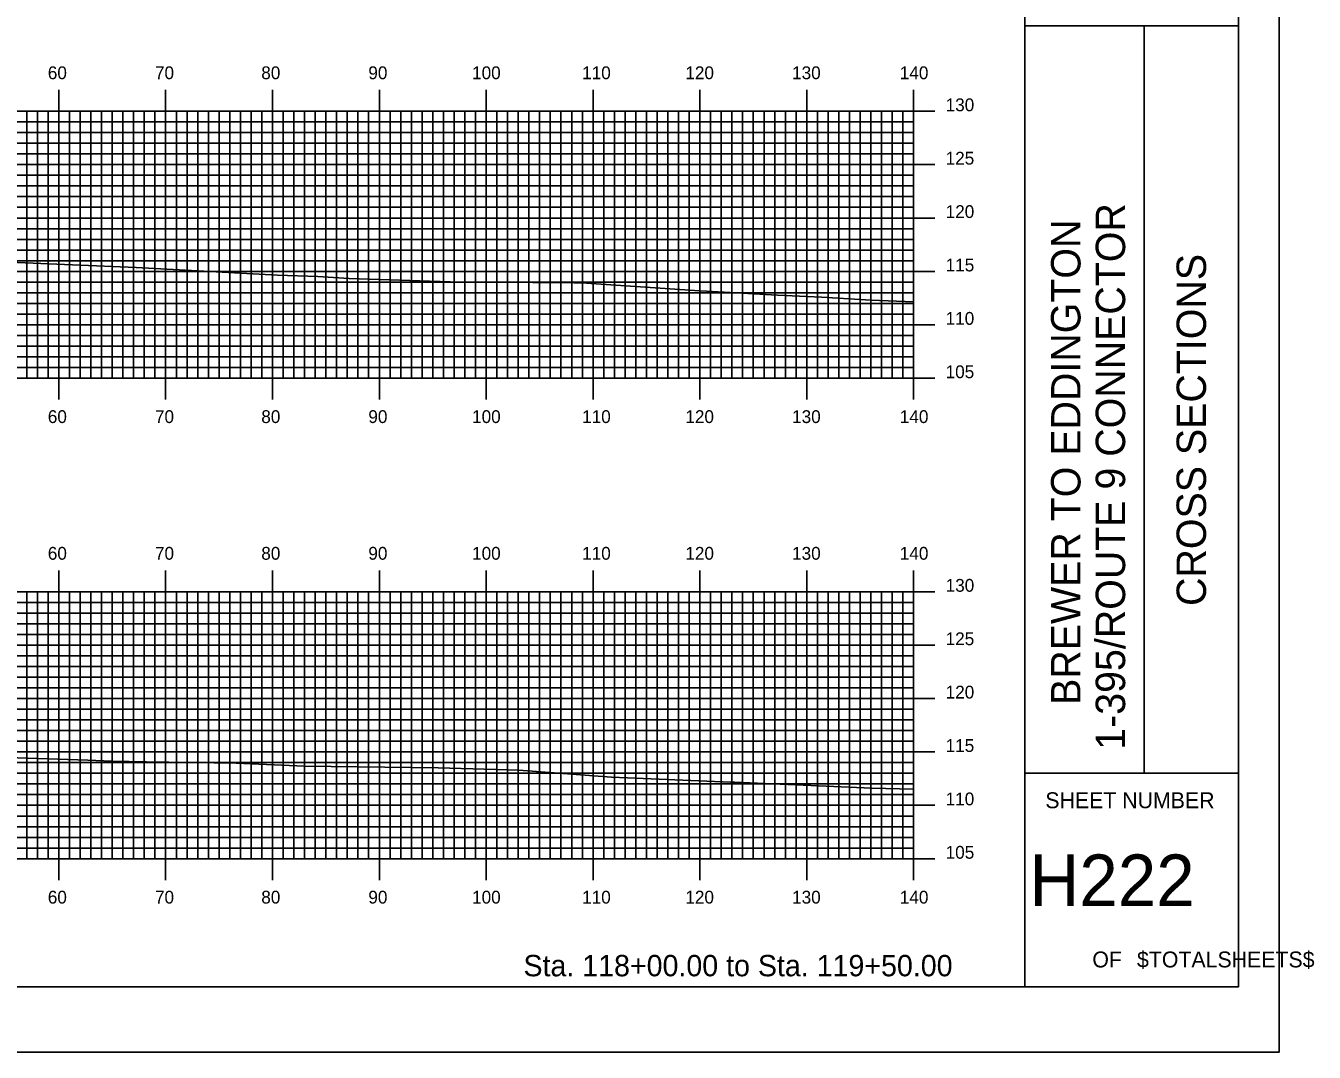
# Model space of a CAD drawing. Extents: x 1771629 to 1771972, y 442591 to 442811.
# Drawn here: x 1771851.5 to 1771972.1, y 442590.5 to 442686.7 of the extents above; entities that cross this region are included whole.
import ezdxf

# ---------------------------------------------------------------- set-up
doc = ezdxf.new("R2010")
doc.units = 0
for name, color, linetype in [('BORDER', 7, 'Continuous'), ('H_V ANNOTATION', 7, 'Continuous'), ('MAJOR', 7, 'Continuous'), ('MINOR', 7, 'Continuous'), ('PLOT BOUNDARY', 7, 'Continuous'), ('S_Roadway_Centerline', 7, 'Continuous')]:
    doc.layers.add(name, color=color, linetype=linetype)

msp = doc.modelspace()

# ---------------------------------------------------------------- linework, layer by layer
at = {"layer": 'BORDER'}
for p, q in [((1771944.98, 442596.67), (1771944.98, 442806.67)), ((1771944.98, 442686.67), (1771964.98, 442686.67)), ((1771956.16, 442616.67), (1771956.16, 442686.67)), ((1771944.98, 442616.67), (1771964.98, 442616.67))]:
    msp.add_line(p, q, dxfattribs=at)
msp.add_lwpolyline([(1771644.98, 442596.67), (1771964.98, 442596.67), (1771964.98, 442806.67), (1771644.98, 442806.67)], close=True, dxfattribs=at)
at = {"layer": 'MAJOR'}
for p, q in [((1771854.58, 442680.67), (1771854.58, 442678.67)), ((1771864.58, 442680.67), (1771864.58, 442678.67)), ((1771874.58, 442680.67), (1771874.58, 442678.67)), ((1771884.58, 442680.67), (1771884.58, 442678.67)), ((1771894.58, 442680.67), (1771894.58, 442678.67)), ((1771904.58, 442680.67), (1771904.58, 442678.67)), ((1771914.58, 442680.67), (1771914.58, 442678.67)), ((1771924.58, 442680.67), (1771924.58, 442678.67)), ((1771934.58, 442680.67), (1771934.58, 442678.67)), ((1771654.58, 442678.67), (1771934.58, 442678.67)), ((1771654.58, 442678.67), (1771934.58, 442678.67)), ((1771854.58, 442653.67), (1771854.58, 442678.67)), ((1771864.58, 442653.67), (1771864.58, 442678.67)), ((1771874.58, 442653.67), (1771874.58, 442678.67)), ((1771884.58, 442653.67), (1771884.58, 442678.67)), ((1771894.58, 442653.67), (1771894.58, 442678.67)), ((1771904.58, 442653.67), (1771904.58, 442678.67)), ((1771914.58, 442653.67), (1771914.58, 442678.67)), ((1771924.58, 442653.67), (1771924.58, 442678.67)), ((1771936.58, 442678.67), (1771932.58, 442678.67)), ((1771934.58, 442653.67), (1771934.58, 442678.67)), ((1771934.58, 442653.67), (1771934.58, 442678.67)), ((1771654.58, 442673.67), (1771934.58, 442673.67)), ((1771936.58, 442673.67), (1771932.58, 442673.67)), ((1771654.58, 442668.67), (1771934.58, 442668.67)), ((1771936.58, 442668.67), (1771932.58, 442668.67)), ((1771654.58, 442663.67), (1771934.58, 442663.67)), ((1771936.58, 442663.67), (1771932.58, 442663.67)), ((1771654.58, 442658.67), (1771934.58, 442658.67)), ((1771936.58, 442658.67), (1771932.58, 442658.67)), ((1771654.58, 442653.67), (1771934.58, 442653.67)), ((1771654.58, 442653.67), (1771934.58, 442653.67)), ((1771854.58, 442651.66), (1771854.58, 442653.67)), ((1771864.58, 442651.66), (1771864.58, 442653.67)), ((1771874.58, 442651.66), (1771874.58, 442653.67)), ((1771884.58, 442651.66), (1771884.58, 442653.67)), ((1771894.58, 442651.66), (1771894.58, 442653.67)), ((1771904.58, 442651.66), (1771904.58, 442653.67)), ((1771914.58, 442651.66), (1771914.58, 442653.67)), ((1771924.58, 442651.66), (1771924.58, 442653.67)), ((1771936.58, 442653.67), (1771932.58, 442653.67)), ((1771934.58, 442651.66), (1771934.58, 442653.67)), ((1771854.58, 442635.67), (1771854.58, 442633.67)), ((1771864.58, 442635.67), (1771864.58, 442633.67)), ((1771874.58, 442635.67), (1771874.58, 442633.67)), ((1771884.58, 442635.67), (1771884.58, 442633.67)), ((1771894.58, 442635.67), (1771894.58, 442633.67)), ((1771904.58, 442635.67), (1771904.58, 442633.67)), ((1771914.58, 442635.67), (1771914.58, 442633.67)), ((1771924.58, 442635.67), (1771924.58, 442633.67)), ((1771934.58, 442635.67), (1771934.58, 442633.67)), ((1771654.58, 442633.67), (1771934.58, 442633.67)), ((1771654.58, 442633.67), (1771934.58, 442633.67)), ((1771854.58, 442608.67), (1771854.58, 442633.67)), ((1771864.58, 442608.67), (1771864.58, 442633.67)), ((1771874.58, 442608.67), (1771874.58, 442633.67)), ((1771884.58, 442608.67), (1771884.58, 442633.67)), ((1771894.58, 442608.67), (1771894.58, 442633.67)), ((1771904.58, 442608.67), (1771904.58, 442633.67)), ((1771914.58, 442608.67), (1771914.58, 442633.67)), ((1771924.58, 442608.67), (1771924.58, 442633.67)), ((1771936.58, 442633.67), (1771932.58, 442633.67)), ((1771934.58, 442608.67), (1771934.58, 442633.67)), ((1771934.58, 442608.67), (1771934.58, 442633.67)), ((1771654.58, 442628.67), (1771934.58, 442628.67)), ((1771936.58, 442628.67), (1771932.58, 442628.67)), ((1771654.58, 442623.67), (1771934.58, 442623.67)), ((1771936.58, 442623.67), (1771932.58, 442623.67)), ((1771654.58, 442618.67), (1771934.58, 442618.67)), ((1771936.58, 442618.67), (1771932.58, 442618.67)), ((1771654.58, 442613.67), (1771934.58, 442613.67)), ((1771936.58, 442613.67), (1771932.58, 442613.67)), ((1771654.58, 442608.67), (1771934.58, 442608.67)), ((1771654.58, 442608.67), (1771934.58, 442608.67)), ((1771854.58, 442606.66), (1771854.58, 442608.67)), ((1771864.58, 442606.66), (1771864.58, 442608.67)), ((1771874.58, 442606.66), (1771874.58, 442608.67)), ((1771884.58, 442606.66), (1771884.58, 442608.67)), ((1771894.58, 442606.66), (1771894.58, 442608.67)), ((1771904.58, 442606.66), (1771904.58, 442608.67)), ((1771914.58, 442606.66), (1771914.58, 442608.67)), ((1771924.58, 442606.66), (1771924.58, 442608.67)), ((1771936.58, 442608.67), (1771932.58, 442608.67)), ((1771934.58, 442606.66), (1771934.58, 442608.67))]:
    msp.add_line(p, q, dxfattribs=at)
at = {"layer": 'MINOR'}
for p, q in [((1771851.58, 442653.67), (1771851.58, 442678.67)), ((1771852.58, 442653.67), (1771852.58, 442678.67)), ((1771853.58, 442653.67), (1771853.58, 442678.67)), ((1771855.58, 442653.67), (1771855.58, 442678.67)), ((1771856.58, 442653.67), (1771856.58, 442678.67)), ((1771857.58, 442653.67), (1771857.58, 442678.67)), ((1771858.58, 442653.67), (1771858.58, 442678.67)), ((1771859.58, 442653.67), (1771859.58, 442678.67)), ((1771860.58, 442653.67), (1771860.58, 442678.67)), ((1771861.58, 442653.67), (1771861.58, 442678.67)), ((1771862.58, 442653.67), (1771862.58, 442678.67)), ((1771863.58, 442653.67), (1771863.58, 442678.67)), ((1771865.58, 442653.67), (1771865.58, 442678.67)), ((1771866.58, 442653.67), (1771866.58, 442678.67)), ((1771867.58, 442653.67), (1771867.58, 442678.67)), ((1771868.58, 442653.67), (1771868.58, 442678.67)), ((1771869.58, 442653.67), (1771869.58, 442678.67)), ((1771870.58, 442653.67), (1771870.58, 442678.67)), ((1771871.58, 442653.67), (1771871.58, 442678.67)), ((1771872.58, 442653.67), (1771872.58, 442678.67)), ((1771873.58, 442653.67), (1771873.58, 442678.67)), ((1771875.58, 442653.67), (1771875.58, 442678.67)), ((1771876.58, 442653.67), (1771876.58, 442678.67)), ((1771877.58, 442653.67), (1771877.58, 442678.67)), ((1771878.58, 442653.67), (1771878.58, 442678.67)), ((1771879.58, 442653.67), (1771879.58, 442678.67)), ((1771880.58, 442653.67), (1771880.58, 442678.67)), ((1771881.58, 442653.67), (1771881.58, 442678.67)), ((1771882.58, 442653.67), (1771882.58, 442678.67)), ((1771883.58, 442653.67), (1771883.58, 442678.67)), ((1771885.58, 442653.67), (1771885.58, 442678.67)), ((1771886.58, 442653.67), (1771886.58, 442678.67)), ((1771887.58, 442653.67), (1771887.58, 442678.67)), ((1771888.58, 442653.67), (1771888.58, 442678.67)), ((1771889.58, 442653.67), (1771889.58, 442678.67)), ((1771890.58, 442653.67), (1771890.58, 442678.67)), ((1771891.58, 442653.67), (1771891.58, 442678.67)), ((1771892.58, 442653.67), (1771892.58, 442678.67)), ((1771893.58, 442653.67), (1771893.58, 442678.67)), ((1771895.58, 442653.67), (1771895.58, 442678.67)), ((1771896.58, 442653.67), (1771896.58, 442678.67)), ((1771897.58, 442653.67), (1771897.58, 442678.67)), ((1771898.58, 442653.67), (1771898.58, 442678.67)), ((1771899.58, 442653.67), (1771899.58, 442678.67)), ((1771900.58, 442653.67), (1771900.58, 442678.67)), ((1771901.58, 442653.67), (1771901.58, 442678.67)), ((1771902.58, 442653.67), (1771902.58, 442678.67)), ((1771903.58, 442653.67), (1771903.58, 442678.67)), ((1771905.58, 442653.67), (1771905.58, 442678.67)), ((1771906.58, 442653.67), (1771906.58, 442678.67)), ((1771907.58, 442653.67), (1771907.58, 442678.67)), ((1771908.58, 442653.67), (1771908.58, 442678.67)), ((1771909.58, 442653.67), (1771909.58, 442678.67)), ((1771910.58, 442653.67), (1771910.58, 442678.67)), ((1771911.58, 442653.67), (1771911.58, 442678.67)), ((1771912.58, 442653.67), (1771912.58, 442678.67)), ((1771913.58, 442653.67), (1771913.58, 442678.67)), ((1771915.58, 442653.67), (1771915.58, 442678.67)), ((1771916.58, 442653.67), (1771916.58, 442678.67)), ((1771917.58, 442653.67), (1771917.58, 442678.67)), ((1771918.58, 442653.67), (1771918.58, 442678.67)), ((1771919.58, 442653.67), (1771919.58, 442678.67)), ((1771920.58, 442653.67), (1771920.58, 442678.67)), ((1771921.58, 442653.67), (1771921.58, 442678.67)), ((1771922.58, 442653.67), (1771922.58, 442678.67)), ((1771923.58, 442653.67), (1771923.58, 442678.67)), ((1771925.58, 442653.67), (1771925.58, 442678.67)), ((1771926.58, 442653.67), (1771926.58, 442678.67)), ((1771927.58, 442653.67), (1771927.58, 442678.67)), ((1771928.58, 442653.67), (1771928.58, 442678.67)), ((1771929.58, 442653.67), (1771929.58, 442678.67)), ((1771930.58, 442653.67), (1771930.58, 442678.67)), ((1771931.58, 442653.67), (1771931.58, 442678.67)), ((1771932.58, 442653.67), (1771932.58, 442678.67)), ((1771933.58, 442653.67), (1771933.58, 442678.67)), ((1771654.58, 442677.67), (1771934.58, 442677.67)), ((1771934.58, 442677.67), (1771932.58, 442677.67)), ((1771654.58, 442676.67), (1771934.58, 442676.67)), ((1771654.58, 442675.67), (1771934.58, 442675.67)), ((1771934.58, 442676.67), (1771932.58, 442676.67)), ((1771934.58, 442675.67), (1771932.58, 442675.67)), ((1771654.58, 442674.67), (1771934.58, 442674.67)), ((1771934.58, 442674.67), (1771932.58, 442674.67)), ((1771654.58, 442672.67), (1771934.58, 442672.67)), ((1771934.58, 442672.67), (1771932.58, 442672.67)), ((1771654.58, 442671.67), (1771934.58, 442671.67)), ((1771934.58, 442671.67), (1771932.58, 442671.67)), ((1771654.58, 442670.67), (1771934.58, 442670.67)), ((1771654.58, 442669.67), (1771934.58, 442669.67)), ((1771934.58, 442670.67), (1771932.58, 442670.67)), ((1771934.58, 442669.67), (1771932.58, 442669.67)), ((1771654.58, 442667.67), (1771934.58, 442667.67)), ((1771934.58, 442667.67), (1771932.58, 442667.67)), ((1771654.58, 442666.67), (1771934.58, 442666.67)), ((1771934.58, 442666.67), (1771932.58, 442666.67)), ((1771654.58, 442665.67), (1771934.58, 442665.67)), ((1771934.58, 442665.67), (1771932.58, 442665.67)), ((1771654.58, 442664.67), (1771934.58, 442664.67)), ((1771934.58, 442664.67), (1771932.58, 442664.67)), ((1771654.58, 442662.67), (1771934.58, 442662.67)), ((1771934.58, 442662.67), (1771932.58, 442662.67)), ((1771654.58, 442661.67), (1771934.58, 442661.67)), ((1771934.58, 442661.67), (1771932.58, 442661.67)), ((1771654.58, 442660.67), (1771934.58, 442660.67)), ((1771934.58, 442660.67), (1771932.58, 442660.67)), ((1771654.58, 442659.67), (1771934.58, 442659.67)), ((1771934.58, 442659.67), (1771932.58, 442659.67)), ((1771654.58, 442657.67), (1771934.58, 442657.67)), ((1771934.58, 442657.67), (1771932.58, 442657.67)), ((1771654.58, 442656.67), (1771934.58, 442656.67)), ((1771934.58, 442656.67), (1771932.58, 442656.67)), ((1771654.58, 442655.67), (1771934.58, 442655.67)), ((1771934.58, 442655.67), (1771932.58, 442655.67)), ((1771654.58, 442654.67), (1771934.58, 442654.67)), ((1771934.58, 442654.67), (1771932.58, 442654.67)), ((1771851.58, 442608.67), (1771851.58, 442633.67)), ((1771852.58, 442608.67), (1771852.58, 442633.67)), ((1771853.58, 442608.67), (1771853.58, 442633.67)), ((1771855.58, 442608.67), (1771855.58, 442633.67)), ((1771856.58, 442608.67), (1771856.58, 442633.67)), ((1771857.58, 442608.67), (1771857.58, 442633.67)), ((1771858.58, 442608.67), (1771858.58, 442633.67)), ((1771859.58, 442608.67), (1771859.58, 442633.67)), ((1771860.58, 442608.67), (1771860.58, 442633.67)), ((1771861.58, 442608.67), (1771861.58, 442633.67)), ((1771862.58, 442608.67), (1771862.58, 442633.67)), ((1771863.58, 442608.67), (1771863.58, 442633.67)), ((1771865.58, 442608.67), (1771865.58, 442633.67)), ((1771866.58, 442608.67), (1771866.58, 442633.67)), ((1771867.58, 442608.67), (1771867.58, 442633.67)), ((1771868.58, 442608.67), (1771868.58, 442633.67)), ((1771869.58, 442608.67), (1771869.58, 442633.67)), ((1771870.58, 442608.67), (1771870.58, 442633.67)), ((1771871.58, 442608.67), (1771871.58, 442633.67)), ((1771872.58, 442608.67), (1771872.58, 442633.67)), ((1771873.58, 442608.67), (1771873.58, 442633.67)), ((1771875.58, 442608.67), (1771875.58, 442633.67)), ((1771876.58, 442608.67), (1771876.58, 442633.67)), ((1771877.58, 442608.67), (1771877.58, 442633.67)), ((1771878.58, 442608.67), (1771878.58, 442633.67)), ((1771879.58, 442608.67), (1771879.58, 442633.67)), ((1771880.58, 442608.67), (1771880.58, 442633.67)), ((1771881.58, 442608.67), (1771881.58, 442633.67)), ((1771882.58, 442608.67), (1771882.58, 442633.67)), ((1771883.58, 442608.67), (1771883.58, 442633.67)), ((1771885.58, 442608.67), (1771885.58, 442633.67)), ((1771886.58, 442608.67), (1771886.58, 442633.67)), ((1771887.58, 442608.67), (1771887.58, 442633.67)), ((1771888.58, 442608.67), (1771888.58, 442633.67)), ((1771889.58, 442608.67), (1771889.58, 442633.67)), ((1771890.58, 442608.67), (1771890.58, 442633.67)), ((1771891.58, 442608.67), (1771891.58, 442633.67)), ((1771892.58, 442608.67), (1771892.58, 442633.67)), ((1771893.58, 442608.67), (1771893.58, 442633.67)), ((1771895.58, 442608.67), (1771895.58, 442633.67)), ((1771896.58, 442608.67), (1771896.58, 442633.67)), ((1771897.58, 442608.67), (1771897.58, 442633.67)), ((1771898.58, 442608.67), (1771898.58, 442633.67)), ((1771899.58, 442608.67), (1771899.58, 442633.67)), ((1771900.58, 442608.67), (1771900.58, 442633.67)), ((1771901.58, 442608.67), (1771901.58, 442633.67)), ((1771902.58, 442608.67), (1771902.58, 442633.67)), ((1771903.58, 442608.67), (1771903.58, 442633.67)), ((1771905.58, 442608.67), (1771905.58, 442633.67)), ((1771906.58, 442608.67), (1771906.58, 442633.67)), ((1771907.58, 442608.67), (1771907.58, 442633.67)), ((1771908.58, 442608.67), (1771908.58, 442633.67)), ((1771909.58, 442608.67), (1771909.58, 442633.67)), ((1771910.58, 442608.67), (1771910.58, 442633.67)), ((1771911.58, 442608.67), (1771911.58, 442633.67)), ((1771912.58, 442608.67), (1771912.58, 442633.67)), ((1771913.58, 442608.67), (1771913.58, 442633.67)), ((1771915.58, 442608.67), (1771915.58, 442633.67)), ((1771916.58, 442608.67), (1771916.58, 442633.67)), ((1771917.58, 442608.67), (1771917.58, 442633.67)), ((1771918.58, 442608.67), (1771918.58, 442633.67)), ((1771919.58, 442608.67), (1771919.58, 442633.67)), ((1771920.58, 442608.67), (1771920.58, 442633.67)), ((1771921.58, 442608.67), (1771921.58, 442633.67)), ((1771922.58, 442608.67), (1771922.58, 442633.67)), ((1771923.58, 442608.67), (1771923.58, 442633.67)), ((1771925.58, 442608.67), (1771925.58, 442633.67)), ((1771926.58, 442608.67), (1771926.58, 442633.67)), ((1771927.58, 442608.67), (1771927.58, 442633.67)), ((1771928.58, 442608.67), (1771928.58, 442633.67)), ((1771929.58, 442608.67), (1771929.58, 442633.67)), ((1771930.58, 442608.67), (1771930.58, 442633.67)), ((1771931.58, 442608.67), (1771931.58, 442633.67)), ((1771932.58, 442608.67), (1771932.58, 442633.67)), ((1771933.58, 442608.67), (1771933.58, 442633.67)), ((1771654.58, 442632.67), (1771934.58, 442632.67)), ((1771934.58, 442632.67), (1771932.58, 442632.67)), ((1771654.58, 442631.67), (1771934.58, 442631.67)), ((1771934.58, 442631.67), (1771932.58, 442631.67)), ((1771654.58, 442630.67), (1771934.58, 442630.67)), ((1771934.58, 442630.67), (1771932.58, 442630.67)), ((1771654.58, 442629.67), (1771934.58, 442629.67)), ((1771934.58, 442629.67), (1771932.58, 442629.67)), ((1771654.58, 442627.67), (1771934.58, 442627.67)), ((1771934.58, 442627.67), (1771932.58, 442627.67)), ((1771654.58, 442626.67), (1771934.58, 442626.67)), ((1771934.58, 442626.67), (1771932.58, 442626.67)), ((1771654.58, 442625.67), (1771934.58, 442625.67)), ((1771934.58, 442625.67), (1771932.58, 442625.67)), ((1771654.58, 442624.67), (1771934.58, 442624.67)), ((1771934.58, 442624.67), (1771932.58, 442624.67)), ((1771654.58, 442622.67), (1771934.58, 442622.67)), ((1771934.58, 442622.67), (1771932.58, 442622.67)), ((1771654.58, 442621.67), (1771934.58, 442621.67)), ((1771934.58, 442621.67), (1771932.58, 442621.67)), ((1771654.58, 442620.67), (1771934.58, 442620.67)), ((1771934.58, 442620.67), (1771932.58, 442620.67)), ((1771654.58, 442619.67), (1771934.58, 442619.67)), ((1771934.58, 442619.67), (1771932.58, 442619.67)), ((1771654.58, 442617.67), (1771934.58, 442617.67)), ((1771654.58, 442616.67), (1771934.58, 442616.67)), ((1771934.58, 442617.67), (1771932.58, 442617.67)), ((1771934.58, 442616.67), (1771932.58, 442616.67)), ((1771654.58, 442615.67), (1771934.58, 442615.67)), ((1771934.58, 442615.67), (1771932.58, 442615.67)), ((1771654.58, 442614.67), (1771934.58, 442614.67)), ((1771934.58, 442614.67), (1771932.58, 442614.67)), ((1771654.58, 442612.67), (1771934.58, 442612.67)), ((1771934.58, 442612.67), (1771932.58, 442612.67)), ((1771654.58, 442611.67), (1771934.58, 442611.67)), ((1771654.58, 442610.67), (1771934.58, 442610.67)), ((1771934.58, 442611.67), (1771932.58, 442611.67)), ((1771934.58, 442610.67), (1771932.58, 442610.67)), ((1771654.58, 442609.67), (1771934.58, 442609.67)), ((1771934.58, 442609.67), (1771932.58, 442609.67))]:
    msp.add_line(p, q, dxfattribs=at)
at = {"layer": 'PLOT BOUNDARY'}
msp.add_lwpolyline([(1771628.79, 442590.55), (1771968.79, 442590.55), (1771968.79, 442810.55), (1771628.79, 442810.55)], close=True, dxfattribs=at)
at = {"layer": 'S_Roadway_Centerline'}
for points in [[(1771847.73, 442664.62), (1771855.87, 442664.27), (1771861.83, 442664.05), (1771875.06, 442663.33), (1771878.83, 442663.18), (1771881.75, 442663.01), (1771891.22, 442662.69), (1771902.81, 442662.6), (1771903.51, 442662.59), (1771914.06, 442661.89), (1771921.85, 442661.46), (1771925.96, 442661.25), (1771930.6, 442660.99), (1771934.58, 442660.81)], [(1771847.9, 442618.21), (1771857.29, 442617.89), (1771859.55, 442617.8), (1771862.78, 442617.73), (1771871.17, 442617.61), (1771877.59, 442617.34), (1771890.07, 442617.17), (1771897.62, 442616.96), (1771906.3, 442616.32), (1771917.43, 442615.85), (1771917.58, 442615.85), (1771917.82, 442615.84), (1771930.67, 442615.28), (1771934.58, 442615.18)]]:
    msp.add_lwpolyline(points, dxfattribs=at)

# ---------------------------------------------------------------- texts
at = {"layer": 'BORDER'}
for s, p in [('1-395/ROUTE 9 CONNECTOR', (1771954.38, 442618.87)), ('BREWER TO EDDINGTON', (1771950.2, 442623.07)), ('CROSS SECTIONS', (1771961.95, 442632.34))]:
    msp.add_text(s, height=2.7557, rotation=90, dxfattribs=at).set_placement(p)
for s, height, p in [('SHEET NUMBER', 1.4905, (1771946.91, 442613.4)), ('H222', 4.839, (1771945.42, 442604.23)), ('OF', 1.491, (1771951.31, 442598.49)), ('$TOTALSHEETS$', 1.4905, (1771955.49, 442598.49))]:
    msp.add_text(s, height=height, dxfattribs=at).set_placement(p)
at = {"layer": 'H_V ANNOTATION'}
for s, height, p in [('60', 1.2, (1771853.55, 442681.67)), ('70', 1.2, (1771863.58, 442681.67)), ('80', 1.2, (1771873.53, 442681.67)), ('90', 1.2, (1771883.55, 442681.67)), ('100', 1.2, (1771893.26, 442681.67)), ('110', 1.2, (1771903.56, 442681.67)), ('120', 1.2, (1771913.22, 442681.67)), ('130', 1.2, (1771923.21, 442681.67)), ('140', 1.2, (1771933.29, 442681.67)), ('130', 1.2, (1771937.58, 442678.67)), ('125', 1.2, (1771937.58, 442673.67)), ('120', 1.2, (1771937.58, 442668.67)), ('115', 1.2, (1771937.58, 442663.67)), ('110', 1.2, (1771937.58, 442658.67)), ('105', 1.2, (1771937.58, 442653.67)), ('60', 1.2, (1771853.55, 442649.47)), ('70', 1.2, (1771863.58, 442649.47)), ('80', 1.2, (1771873.53, 442649.47)), ('90', 1.2, (1771883.55, 442649.47)), ('100', 1.2, (1771893.26, 442649.47)), ('110', 1.2, (1771903.56, 442649.47)), ('120', 1.2, (1771913.22, 442649.47)), ('130', 1.2, (1771923.21, 442649.47)), ('140', 1.2, (1771933.29, 442649.47)), ('60', 1.2, (1771853.55, 442636.67)), ('70', 1.2, (1771863.58, 442636.67)), ('80', 1.2, (1771873.53, 442636.67)), ('90', 1.2, (1771883.55, 442636.67)), ('100', 1.2, (1771893.26, 442636.67)), ('110', 1.2, (1771903.56, 442636.67)), ('120', 1.2, (1771913.22, 442636.67)), ('130', 1.2, (1771923.21, 442636.67)), ('140', 1.2, (1771933.29, 442636.67)), ('130', 1.2, (1771937.58, 442633.67)), ('125', 1.2, (1771937.58, 442628.67)), ('120', 1.2, (1771937.58, 442623.67)), ('115', 1.2, (1771937.58, 442618.67)), ('110', 1.2, (1771937.58, 442613.67)), ('105', 1.2, (1771937.58, 442608.67)), ('60', 1.2, (1771853.55, 442604.47)), ('70', 1.2, (1771863.58, 442604.47)), ('80', 1.2, (1771873.53, 442604.47)), ('90', 1.2, (1771883.55, 442604.47)), ('100', 1.2, (1771893.26, 442604.47)), ('110', 1.2, (1771903.56, 442604.47)), ('120', 1.2, (1771913.22, 442604.47)), ('130', 1.2, (1771923.21, 442604.47)), ('140', 1.2, (1771933.29, 442604.47)), ('Sta. 118+00.00 to Sta. 119+50.00', 2.0004, (1771898.07, 442597.66))]:
    msp.add_text(s, height=height, dxfattribs=at).set_placement(p)

doc.saveas('drawing.dxf')
